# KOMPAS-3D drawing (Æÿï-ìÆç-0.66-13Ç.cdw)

Views: Вид 1, Вид 2
Referenced files in W:\Технический отдел\КБ\Рабочая папка\КД\Экспериментальное, тех решения\Испанский датчик\: ТШП-0,66 ГЧ.cdw
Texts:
  max
  Табличка технических
  данных
  Винт М6
  Масса не более 13,9 кг
  ТШЛ-НТЗ-0,66-13 УХЛ2, Т2
  Яковлев
  Михайлов
  Морозов
  Фролова
  Пимурзин
  М.Контр.
  Трансформатор тока
  нулевой последовательности
  ТЗЛК-НТЗ-0,66-70(-100,-125,-205)-01 У2
  Габаритный чертеж
  см. табл.
  НТЗ
  НТЗ.03.14.00.00.000
  Без внутренней рамки.
Dimensions and other numbers on the sheet: 125; 180; 120; 235; 130; 230; 122; 20; 4 шт. max; 3; -7Нх15; 10; 2 отв.; 136; 3х20=60; 1:2; 1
